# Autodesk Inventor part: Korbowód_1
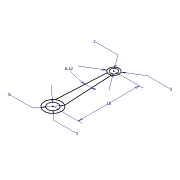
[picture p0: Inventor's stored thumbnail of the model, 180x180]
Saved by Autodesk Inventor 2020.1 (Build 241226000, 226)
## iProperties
Created: 2005-10
Part Number: Korbowód_1
Document SubType Name: Modeling
Designer: F.Stasiak
Density: 1 g/cm^3
Material: Ogólny
Appearance: Domyślna
Manager: www.cadconsulting.pl
Company: Fabian Stasiak CAD Consulting
Subject: Zbiór ćwiczeń. Autodesk Inventor 2020. Kurs podstawowy
Author: F.Stasiak
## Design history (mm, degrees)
sketch "Szkic1"
  geometry: L1 (0.611, 16.63)-(1.389, 2.079); L2 (-0.611, 16.63)-(-1.389, 2.079); C1 r 1 at (0, 18); C2 r 1.5 at (0, 0); A1 r 1.5 centre (0, 18) between (0.611, 16.63) and (-0.611, 16.63); A2 r 2.5 centre (0, 0) between (1.389, 2.079) and (-1.389, 2.079)
  constraints: 4 centre point, 4 end point, 4 point on circle
  dimensions: "d1" = 18 distance of C1.centre A2.centre; "d3" = 6.11792 deg angle of L2 L1; "d5" = 5 diameter of A2; "d7" = 3 diameter of C2; "d9" = 2 diameter of C1; "d11" = 3 diameter of A1
node "Korpusy bryłowe"
node "Korpusy powierzchniowe"
other parameters: "d0" = 18 (derived), "d2" = 1.06778 (derived), "d4" = 5 (derived), "d6" = 3 (derived), "d8" = 2 (derived), "d10" = 3 (derived)
